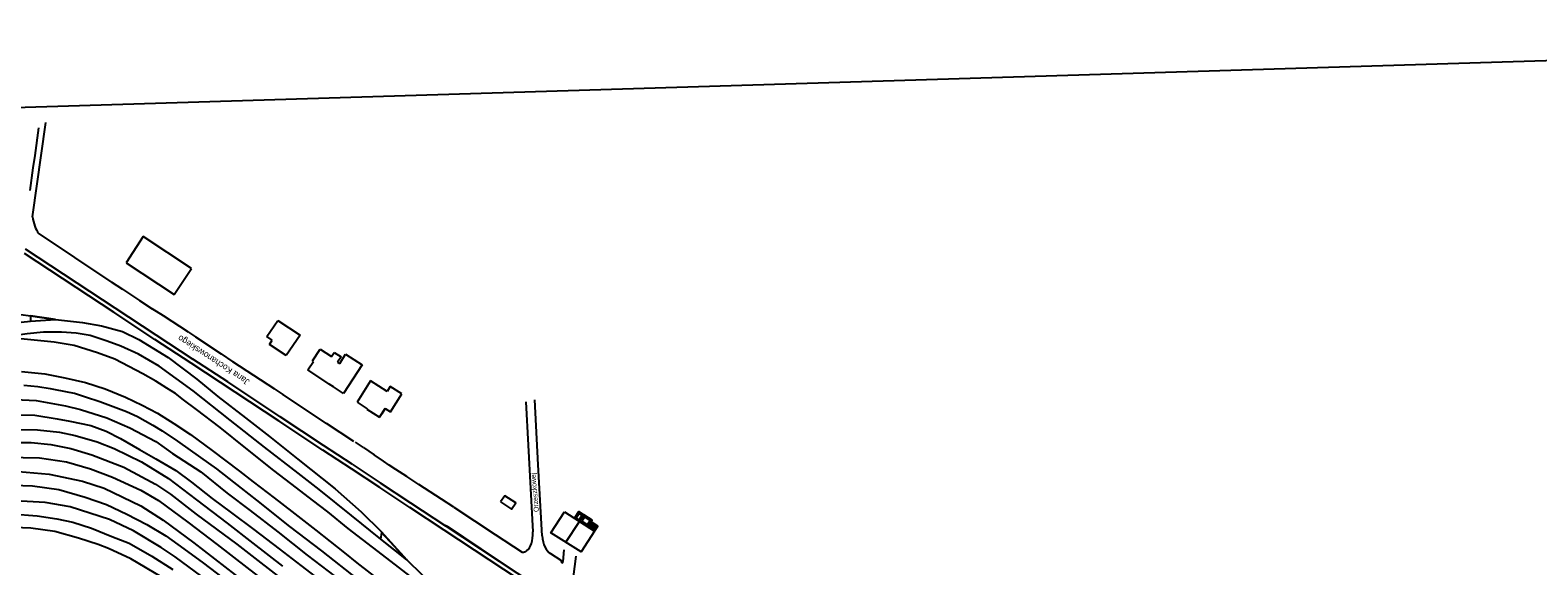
# Model space of a CAD drawing. Extents: x 6541740 to 6566395, y 5525066 to 5530361.
# Drawn here: x 6553961 to 6554203.1, y 5525413.4 to 5525499.4 of the extents above; entities that cross this region are included whole.
import ezdxf

# ---------------------------------------------------------------- set-up
doc = ezdxf.new("R2010")
doc.units = 0
for name, color, linetype in [('ps_wymiarowanie', 7, 'Continuous'), ('TOR_PS_OPIS_T-ukresy', 7, 'Continuous'), ('TOR_PS_P-chodniki i place ładunkowe', 7, 'Continuous'), ('TOR_PS_T-wypelnienia', 7, 'Continuous')]:
    doc.layers.add(name, color=color, linetype=linetype)

msp = doc.modelspace()

# ---------------------------------------------------------------- linework, layer by layer
at = {"layer": 'ps_wymiarowanie'}
for p, q in [((6553979.13, 5525466.25), (6553976.38, 5525462.07)), ((6553986.89, 5525461.15), (6553979.13, 5525466.25)), ((6553976.38, 5525462.07), (6553984.13, 5525456.94)), ((6553984.13, 5525456.94), (6553986.89, 5525461.15)), ((6553998.99, 5525450.21), (6554000.78, 5525452.77)), ((6554000.78, 5525452.77), (6554004.35, 5525450.42)), ((6554004.35, 5525450.42), (6554002.11, 5525447.17)), ((6553999.85, 5525449.63), (6553998.99, 5525450.21)), ((6553999.42, 5525448.96), (6553999.85, 5525449.63)), ((6554002.11, 5525447.17), (6553999.42, 5525448.96)), ((6554006.33, 5525446.32), (6554007.58, 5525448.21)), ((6554007.58, 5525448.21), (6554009.39, 5525447.02)), ((6554005.59, 5525444.87), (6554006.48, 5525446.22)), ((6554006.48, 5525446.22), (6554006.33, 5525446.32)), ((6554009.39, 5525447.02), (6554009.82, 5525447.68)), ((6554009.82, 5525447.68), (6554010.92, 5525446.95)), ((6554010.92, 5525446.95), (6554010.37, 5525446.13)), ((6554010.37, 5525446.13), (6554010.72, 5525445.9)), ((6554010.72, 5525445.9), (6554011.65, 5525447.38)), ((6554014.31, 5525445.67), (6554011.3, 5525441.09)), ((6554011.65, 5525447.38), (6554014.31, 5525445.67)), ((6554009.03, 5525442.6), (6554005.59, 5525444.87)), ((6554015.64, 5525443.09), (6554013.49, 5525439.67)), ((6554018.31, 5525441.4), (6554015.64, 5525443.09)), ((6554009.71, 5525442.15), (6554009.03, 5525442.6)), ((6554011.3, 5525441.09), (6554009.71, 5525442.15)), ((6554018.82, 5525442.2), (6554018.31, 5525441.4)), ((6554020.67, 5525441.03), (6554018.82, 5525442.2)), ((6554018.85, 5525438.12), (6554020.67, 5525441.03)), ((6554013.49, 5525439.67), (6554015.12, 5525438.64)), ((6554015.12, 5525438.64), (6554015.08, 5525438.55)), ((6554015.08, 5525438.55), (6554017.11, 5525437.28)), ((6554017.11, 5525437.28), (6554017.98, 5525438.66)), ((6554017.98, 5525438.66), (6554017.45, 5525437.82)), ((6554017.98, 5525438.66), (6554018.85, 5525438.12))]:
    msp.add_line(p, q, dxfattribs=at)
for points in [[(6554036.54, 5525423.7), (6554038.29, 5525422.51), (6554038.99, 5525423.51), (6554037.21, 5525424.68)], [(6554046.8, 5525422.07), (6554051.61, 5525419), (6554049.48, 5525415.67), (6554044.58, 5525418.71)], [(6554048.39, 5525421.06), (6554049.08, 5525422.13), (6554049.91, 5525421.6), (6554049.23, 5525420.52)], [(6554048.7, 5525421.12), (6554049.15, 5525421.82), (6554049.6, 5525421.53), (6554049.16, 5525420.83)], [(6554050.55, 5525419.68), (6554051.23, 5525420.75), (6554049.91, 5525421.6), (6554049.23, 5525420.52)], [(6554050.48, 5525419.99), (6554050.92, 5525420.69), (6554050.01, 5525421.27), (6554049.56, 5525420.58)], [(6554051.62, 5525419), (6554052.14, 5525419.81), (6554051.07, 5525420.49), (6554050.55, 5525419.68)]]:
    msp.add_lwpolyline(points, close=True, dxfattribs=at)
for points in [[(6554047.01, 5525417.2), (6554049.23, 5525420.52)], [(6554050.78, 5525419.53), (6554051.3, 5525420.35)], [(6554050.99, 5525419.4), (6554051.51, 5525420.21)], [(6554051.19, 5525419.27), (6554051.71, 5525420.08)], [(6554051.4, 5525419.14), (6554051.92, 5525419.95)]]:
    msp.add_lwpolyline(points, dxfattribs=at)
at = {"layer": 'TOR_PS_OPIS_T-ukresy'}
for points in [[(6553957.91, 5525453.96), (6553961.02, 5525453.56), (6553965.05, 5525452.97)], [(6553958.5, 5525452.42), (6553961.06, 5525452.71), (6553965.05, 5525452.97), (6553969.37, 5525452.49), (6553972.44, 5525451.95), (6553975.79, 5525451.02), (6553978.46, 5525449.75), (6553983.13, 5525446.85), (6553987.76, 5525443.38), (6553991.12, 5525440.62), (6553995.57, 5525437.2), (6553999.41, 5525434.16), (6554003.95, 5525430.56), (6554009.99, 5525425.77), (6554014.15, 5525422.11), (6554017.33, 5525418.91), (6554021.46, 5525414.39), (6554023.9, 5525412.05), (6554027.23, 5525408.7), (6554030.92, 5525404.83)], [(6554021.46, 5525414.39), (6554017.29, 5525417.7), (6554012.57, 5525421.49), (6554007.4, 5525425.65), (6554004, 5525428.27), (6553998.61, 5525432.48), (6553993.09, 5525436.81), (6553987.17, 5525441.49), (6553981.71, 5525445.46), (6553978.36, 5525447.4), (6553975.54, 5525448.7), (6553973.37, 5525449.46), (6553970.63, 5525450.37), (6553968.35, 5525450.74), (6553966.03, 5525450.92), (6553964.41, 5525450.92), (6553963.14, 5525450.94), (6553960.48, 5525450.68), (6553956.83, 5525450.14)], [(6553982.93, 5525441.93), (6553981.17, 5525443.06), (6553979.06, 5525444.26), (6553974.6, 5525446.57), (6553971.81, 5525447.59), (6553968.05, 5525448.78), (6553964.83, 5525449.34), (6553956.83, 5525450.14), (6553954.13, 5525450.04), (6553950.89, 5525449.76), (6553949.47, 5525449.63), (6553945.3, 5525449.26)], [(6553959.58, 5525444.59), (6553963.32, 5525444.21), (6553966.55, 5525443.6), (6553969.89, 5525442.87), (6553973.03, 5525441.84), (6553976.27, 5525440.51), (6553978.97, 5525439.22), (6553981.41, 5525437.94), (6553984.07, 5525436.24), (6553986.75, 5525434.49), (6553990.2, 5525431.96), (6553994.61, 5525428.62), (6553996.78, 5525426.92), (6554000.18, 5525424.35), (6554003.01, 5525422.12), (6554006.85, 5525419.13), (6554011.47, 5525415.5), (6554013.44, 5525413.89), (6554017.23, 5525410.99)], [(6553959.95, 5525442.43), (6553962.21, 5525442.18), (6553964.18, 5525441.86), (6553967.19, 5525441.31), (6553968.11, 5525441.13), (6553969.87, 5525440.55), (6553972.19, 5525439.82), (6553976.45, 5525438.17), (6553978.21, 5525437.37), (6553980.67, 5525436.02), (6553982.2, 5525435.09), (6553984.63, 5525433.43), (6553988.36, 5525430.81), (6553990.9, 5525428.99), (6553994.87, 5525425.89), (6553997.31, 5525423.97), (6554002.65, 5525419.73), (6554007.77, 5525415.82), (6554013.63, 5525411.22)], [(6553987.69, 5525438.52), (6553985.6, 5525440.09), (6553984.32, 5525441.06), (6553982.93, 5525441.93)], [(6553958.56, 5525440.11), (6553961.96, 5525439.96), (6553966.64, 5525439.11), (6553969.09, 5525438.52), (6553973.29, 5525437.18), (6553977, 5525435.55), (6553981.16, 5525433.38), (6553983.83, 5525431.45), (6553988.39, 5525428.5), (6553992.63, 5525425.09), (6553996.3, 5525422.32), (6554000.76, 5525418.87), (6554005.48, 5525415.12), (6554009.97, 5525411.74)], [(6553995.62, 5525432.33), (6553991.49, 5525435.65), (6553987.69, 5525438.52)], [(6553958.09, 5525437.64), (6553961.71, 5525437.59), (6553965.32, 5525436.99), (6553967.36, 5525436.63), (6553970.74, 5525435.92), (6553973.18, 5525435.01), (6553975.47, 5525433.88), (6553978.52, 5525432.11), (6553981.15, 5525430.62), (6553984.39, 5525428.71), (6553986.91, 5525426.87), (6553990.24, 5525424.25), (6553993.33, 5525421.91), (6553996.92, 5525419.28), (6554000.97, 5525416.15), (6554004.45, 5525413.5), (6554008.34, 5525410.46)], [(6553957.26, 5525435.31), (6553962.18, 5525435.27), (6553965.68, 5525434.85), (6553968.21, 5525434.32), (6553971.77, 5525433.3), (6553974.49, 5525432.25), (6553978.86, 5525430.13), (6553983.22, 5525427.45), (6553987.69, 5525424), (6553992.6, 5525420.25), (6553996.77, 5525417.09), (6554001.49, 5525413.39)], [(6553957.81, 5525433.2), (6553961.12, 5525433.2), (6553964.31, 5525432.87), (6553967.51, 5525432.28), (6553970.87, 5525431.25), (6553976.04, 5525429.27), (6553981.13, 5525426.51), (6553983.52, 5525424.91), (6553987.66, 5525421.71), (6553994.16, 5525416.88), (6554011.97, 5525403.09), (6554019.67, 5525397.08), (6554031.02, 5525388.33), (6554041.03, 5525380.43), (6554047.86, 5525375.02), (6554052.32, 5525371.51), (6554057.46, 5525367.29), (6554063.1, 5525362.78), (6554067.22, 5525360.09)], [(6554008.78, 5525422.08), (6554006.35, 5525423.94), (6554003.78, 5525425.92), (6554000.12, 5525428.73), (6553995.62, 5525432.33)], [(6553957.26, 5525430.87), (6553962.47, 5525430.76), (6553966.83, 5525430.12), (6553970.66, 5525428.99), (6553974.23, 5525427.67), (6553978.75, 5525425.56), (6553981.58, 5525423.92), (6553986.28, 5525420.41), (6553991.01, 5525416.85), (6553995.76, 5525413.16), (6554002.17, 5525408.22), (6554010.83, 5525401.68), (6554019.12, 5525395.04), (6554025.17, 5525390.32), (6554030.93, 5525385.71), (6554039.94, 5525378.69), (6554048.51, 5525371.83), (6554053.58, 5525367.86), (6554056.78, 5525365.43), (6554060.91, 5525362.67)], [(6553959.11, 5525428.56), (6553964.05, 5525428.15), (6553969.39, 5525427.01), (6553972.87, 5525425.87), (6553978.76, 5525423.06), (6553982.37, 5525420.78), (6553987.29, 5525417.11), (6553993.92, 5525411.98), (6553999.74, 5525407.48), (6554007.65, 5525401.43), (6554012, 5525398.03), (6554019.95, 5525391.95), (6554023.99, 5525388.61), (6554030.77, 5525383.42), (6554040.19, 5525376.09), (6554046.68, 5525371.1), (6554050.53, 5525368.02), (6554054.61, 5525365.32)], [(6553958.25, 5525426.39), (6553961.36, 5525426.28), (6553965.59, 5525425.68), (6553969.82, 5525424.42), (6553973.22, 5525423.27), (6553976.5, 5525421.73), (6553979.71, 5525420.05), (6553982.79, 5525418.22), (6553985.64, 5525416.18), (6553988.82, 5525413.83), (6553992.87, 5525410.77)], [(6554042.13, 5525370.68), (6554038.06, 5525373.42), (6554031.66, 5525378.01), (6554024.28, 5525383.74), (6554019.25, 5525387.74), (6554011.49, 5525393.85), (6554002.28, 5525401.19), (6553992.62, 5525408.71), (6553984.26, 5525414.89), (6553982, 5525416.39), (6553977.57, 5525419.04), (6553973.7, 5525420.84), (6553967.42, 5525422.89), (6553963.41, 5525423.59), (6553955.61, 5525424.04)], [(6553957.97, 5525421.75), (6553962.11, 5525421.44), (6553965.27, 5525420.95), (6553967.82, 5525420.44), (6553970.83, 5525419.46), (6553974.12, 5525418.15), (6553976.86, 5525417.08), (6553980.51, 5525415), (6553983.89, 5525412.84)], [(6554027.13, 5525407.81), (6554018.26, 5525414.64), (6554012.06, 5525419.41), (6554008.78, 5525422.08)], [(6554023.09, 5525381.53), (6554019.04, 5525384.13), (6554013.56, 5525387.71), (6554010.91, 5525389.42), (6554004.61, 5525394.27), (6553998.67, 5525399.05), (6553990.75, 5525405.2), (6553987.1, 5525408.07), (6553982.12, 5525411.61), (6553977.14, 5525414.56), (6553973.58, 5525416.19), (6553971.91, 5525416.84), (6553968.75, 5525417.86), (6553964.94, 5525418.91), (6553961.09, 5525419.45), (6553958.41, 5525419.56)]]:
    msp.add_lwpolyline(points, dxfattribs=at)
for points in [[(6553965.05, 5525452.97), (6553961.04, 5525453.56), (6553961.06, 5525452.71)], [(6554021.46, 5525414.39), (6554017.43, 5525418.8), (6554017.24, 5525417.73)]]:
    msp.add_lwpolyline(points, close=True, dxfattribs=at)
at = {"layer": 'TOR_PS_P-chodniki i place ładunkowe'}
msp.add_lwpolyline([(6554371.94, 5525212.51), (6553522.34, 5525186.44), (6553513.53, 5525473.31), (6554363.13, 5525499.38)], close=True, dxfattribs=at)
at = {"layer": 'TOR_PS_T-wypelnienia'}
for p, q in [((6553961.37, 5525469.44), (6553963.51, 5525484.57)), ((6553962.34, 5525483.71), (6553961.72, 5525479.28)), ((6553961.43, 5525477.27), (6553960.92, 5525473.67)), ((6553961.72, 5525479.28), (6553961.43, 5525477.27)), ((6553974.01, 5525458.98), (6553962.33, 5525466.79)), ((6553974.48, 5525454.07), (6553960.1, 5525463.53)), ((6553960.18, 5525464.27), (6553974.6, 5525454.8)), ((6553974.01, 5525458.98), (6553975.8, 5525457.81)), ((6553975.8, 5525457.81), (6553978.06, 5525456.33)), ((6553978.06, 5525456.33), (6553978.57, 5525456)), ((6553978.57, 5525456), (6553980.6, 5525454.66)), ((6553981.02, 5525449.77), (6553974.48, 5525454.07)), ((6553974.6, 5525454.8), (6553981.16, 5525450.49)), ((6553982.4, 5525453.54), (6553980.6, 5525454.66)), ((6553986.41, 5525450.92), (6553982.4, 5525453.54)), ((6553981.16, 5525450.49), (6553987.11, 5525446.59)), ((6553986.41, 5525450.92), (6553987.53, 5525450.17)), ((6553986.84, 5525445.95), (6553981.02, 5525449.77)), ((6553987.53, 5525450.17), (6553991.64, 5525447.47)), ((6554000.99, 5525436.64), (6553986.84, 5525445.95)), ((6553992.72, 5525442.95), (6553987.11, 5525446.59)), ((6553991.64, 5525447.47), (6553993.51, 5525446.18)), ((6554000.3, 5525441.78), (6553993.51, 5525446.18)), ((6554001.13, 5525437.36), (6553992.72, 5525442.95)), ((6554000.3, 5525441.78), (6554001.59, 5525440.93)), ((6554008.6, 5525436.26), (6554001.59, 5525440.93)), ((6554040.6, 5525439.72), (6554041.69, 5525418.86)), ((6554042.58, 5525429.66), (6554042.05, 5525440.07)), ((6554008.01, 5525432.01), (6554000.99, 5525436.64)), ((6554008.11, 5525432.76), (6554001.13, 5525437.36)), ((6554012.99, 5525433.4), (6554008.6, 5525436.26)), ((6554012.57, 5525429.01), (6554008.01, 5525432.01)), ((6554012.72, 5525429.74), (6554008.11, 5525432.76)), ((6554014.52, 5525432.39), (6554013.21, 5525433.26)), ((6554014.52, 5525432.39), (6554016.25, 5525431.23)), ((6554017.72, 5525430.21), (6554016.25, 5525431.23)), ((6554017.12, 5525426), (6554012.57, 5525429.01)), ((6554012.72, 5525429.74), (6554017.2, 5525426.77)), ((6554018.66, 5525429.58), (6554017.72, 5525430.21)), ((6554019.7, 5525428.91), (6554018.66, 5525429.58)), ((6554021.47, 5525427.74), (6554019.7, 5525428.91)), ((6554043.19, 5525418.24), (6554042.58, 5525429.66)), ((6554017.2, 5525426.77), (6554022.08, 5525423.55)), ((6554023.42, 5525426.48), (6554021.47, 5525427.74)), ((6554027.07, 5525424.12), (6554023.42, 5525426.48)), ((6554021.97, 5525422.79), (6554017.12, 5525426)), ((6554029.05, 5525422.82), (6554027.07, 5525424.12)), ((6554027.5, 5525419.14), (6554021.97, 5525422.79)), ((6554022.08, 5525423.55), (6554027.68, 5525419.86)), ((6554029.05, 5525422.82), (6554035.66, 5525418.43)), ((6554041.91, 5525409.63), (6554027.5, 5525419.14)), ((6554027.66, 5525419.97), (6554027.96, 5525419.77)), ((6554042.01, 5525410.39), (6554027.68, 5525419.86)), ((6554027.96, 5525419.77), (6554033.36, 5525416.17)), ((6554035.66, 5525418.43), (6554040.02, 5525415.64)), ((6554033.36, 5525416.17), (6554041.58, 5525410.72)), ((6554044.54, 5525415.39), (6554046.21, 5525414.36)), ((6554046.21, 5525414.36), (6554046.36, 5525413.83)), ((6554046.37, 5525413.84), (6554046.6, 5525414.12)), ((6554046.6, 5525414.12), (6554046.73, 5525415.99)), ((6554048.22, 5525411.68), (6554048.7, 5525414.97))]:
    msp.add_line(p, q, dxfattribs=at)
for centre, major_axis, start_param, end_param in [((6553963.5, 5525470.23), (-0.23, 4.29), 1.727881, 2.475334), ((6554040.18, 5525418.7), (-0.16, 2.97), 3.412791, 4.738568), ((6554044.89, 5525418.63), (-0.18, 3.36), 1.657143, 2.833555), ((6554039.98, 5525419.18), (-0.19, 3.55), 3.05923, 3.468045)]:
    msp.add_ellipse(centre, major_axis=major_axis, ratio=0.510219, start_param=start_param, end_param=end_param, dxfattribs=at)

# ---------------------------------------------------------------- texts
for s, height, rotation, p in [('Jana Kochanowskiego', 1, 146.848, (6553996.31, 5525443.19)), ('Orzeszkowej', 0.8, 95.0569, (6554042.68, 5525422.1))]:
    msp.add_text(s, height=height, rotation=rotation, dxfattribs=at).set_placement(p)

doc.saveas('drawing.dxf')
